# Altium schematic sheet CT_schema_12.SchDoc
size 382 x 278 mm
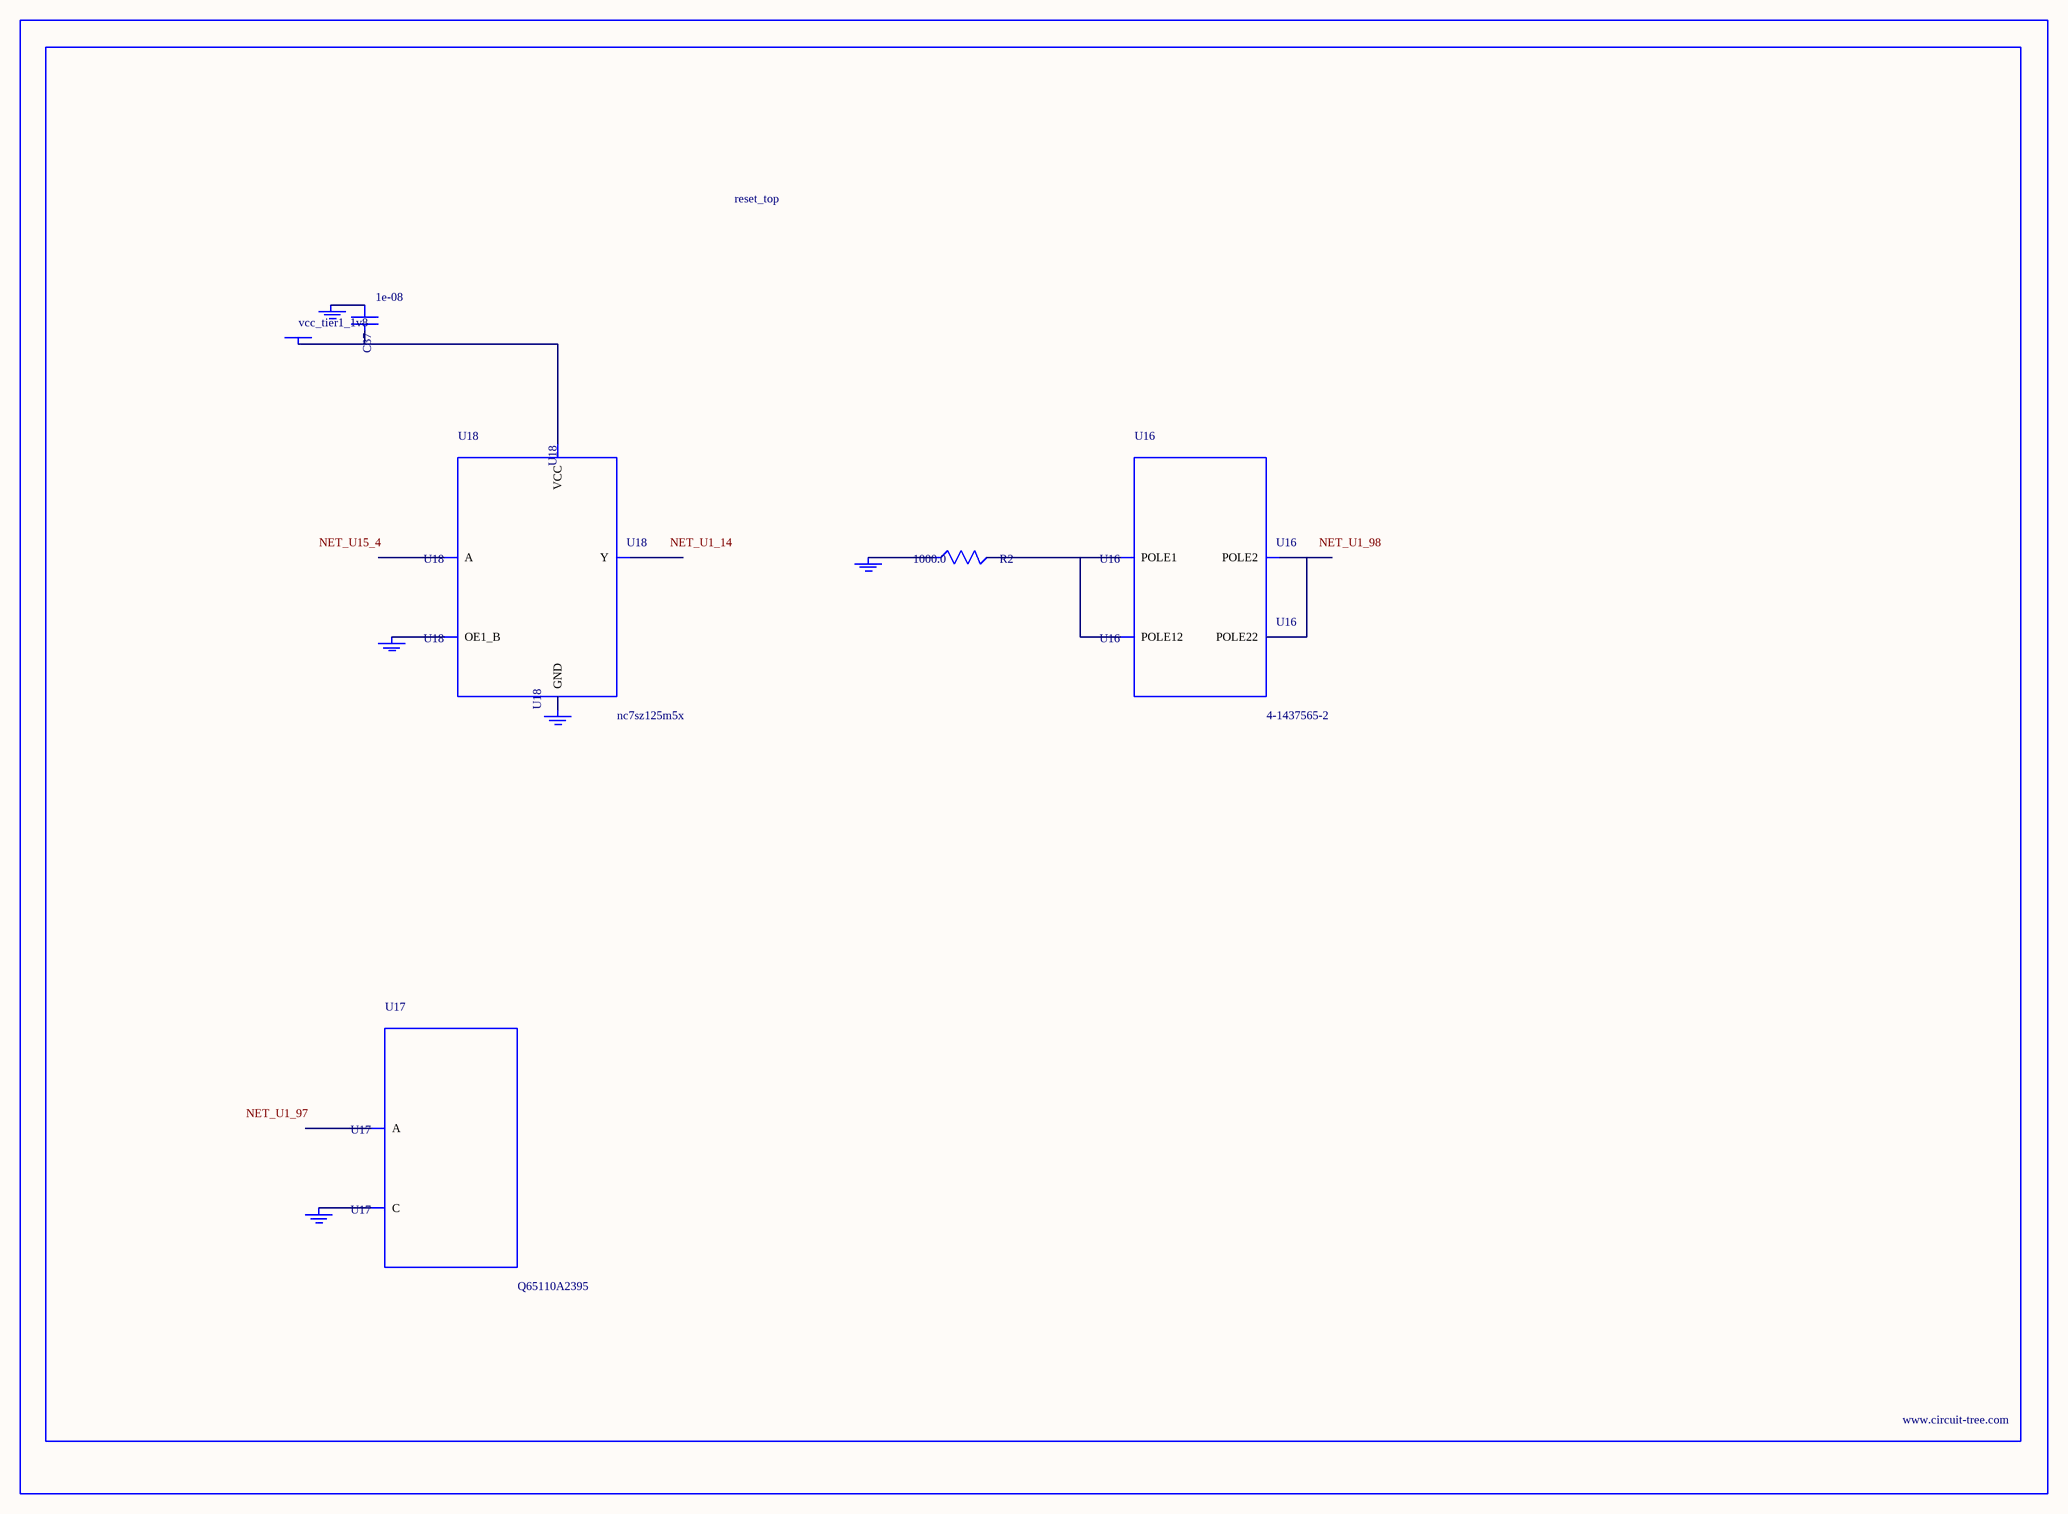
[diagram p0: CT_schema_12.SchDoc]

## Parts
BORDER11  (no value)
C37  1e-08  [C0402]
GND_INSTANCE_11_0  (no value)
GND_INSTANCE_11_1  (no value)
GND_INSTANCE_11_2  (no value)
GND_INSTANCE_11_3  (no value)
GND_INSTANCE_11_4  (no value)
POWER_INSTANCE_11_0  vcc_tier1_1v8
R2  1000.0  [R0603]
U16  4-1437565-2  [SW_4-1437565-2]
U17  Q65110A2395  [LGM67K-G1J2-24-Z]
U18  nc7sz125m5x  [NC7SZ125M5X]

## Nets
NetC37_1: C37.1 GND_INSTANCE_11_2.0(GND)
NetC37_2: C37.2 POWER_INSTANCE_11_0.0(PWR) U18.5(VCC)
NetGND_INSTANCE_11_0_0: GND_INSTANCE_11_0.0(GND) R2.1
NetGND_INSTANCE_11_1_0: GND_INSTANCE_11_1.0(GND) U17.C
NetGND_INSTANCE_11_3_0: GND_INSTANCE_11_3.0(GND) U18.1(OE1_B)
NetGND_INSTANCE_11_4_0: GND_INSTANCE_11_4.0(GND) U18.3(GND)
NetR2_2: R2.2 U16.1(POLE1) U16.2(POLE12)
NetU16_3: U16.3(POLE2) U16.4(POLE22)

Not connected (* = marked no-connect by the designer): U17 A; U18 2(A) 4(Y)

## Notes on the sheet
- Labels drawn without touching a wire or pin: NET_U1_14, NET_U1_97, NET_U1_98, NET_U15_4

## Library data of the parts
BORDER11 = BORDER_PAGE11
C37 = C0402C103K3RAC
GND_INSTANCE_11_0-GND_INSTANCE_11_4 = GND
POWER_INSTANCE_11_0 = PWR
R2 = RC0603JR-071KL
